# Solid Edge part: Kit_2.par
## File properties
Sűrűség: 0,000 kg/m^3
Pontosság: 0,990
Author: bmolnar
Last saved by: bmolnar
Revision: 77
Username: bmolnar
Dokumentum tartalom típus: 0
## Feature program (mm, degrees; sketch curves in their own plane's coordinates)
base feature "unnamed BaseFeature 1"
thread "unnamed Thread 1"
thread "unnamed Thread 2"
thread "unnamed Thread 3"
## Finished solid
Body 1: solid body, 331 faces, 789 edges, 478 vertices, 4 internal voids.
  Faces by surface: plane 145, cylinder 82, swept 53, cone 28, torus 22, spline 1
  Edges by curve: line 445, circle 187, spline 118, ellipse 28, curve on surface 10, intersection 1
Bounding box of the edges (mm; curved faces can reach further): 65.500 x 65.500 x 14.500, from (-32.75, -32.75, 80.5) to (32.75, 32.75, 95).
Cylindrical faces by radius (mm): R0.2 x40, R0.201 x2, R0.2012 x2, R1.75 x1, R2.5402 x12, R2.6 x4, R3.3235 x2, R3.75 x4, R3.85 x4, R4.283 x1, R5 x2, R5.25 x2, R6 x2, R8.27 x1, R8.85 x1, R9 x1, R15.5811 x1
Conical faces (half-angle, radius in mm at the cone's reference point): 0.5 deg R6.5 x2, 0.5 deg R8 x4, 14 deg R8.135 x1, 14 deg R8.4811 x1, 15 deg R5.067 x4, 15 deg R5.933 x4, 17 deg R8.135 x1, 23 deg R8.829 x1, 42.5 deg R8.1233 x1, 45 deg R3.6735 x4, 45 deg R6.05 x2, 45 deg R9 x1, 84 deg R8.4608 x1, 87 deg R8.1765 x1
Toroidal faces (ring radius, tube radius in mm): R2.9402 r0.4 x12, R3.55 r0.2 x8, R8.8057 r0.2025 x1, R9.2522 r0.2925 x1
Planar faces by outward normal: +x 12, +y 14, +z 24, -x 14, -y 14, -z 1, oblique 66
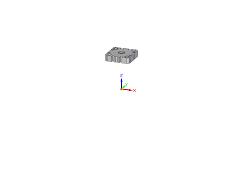
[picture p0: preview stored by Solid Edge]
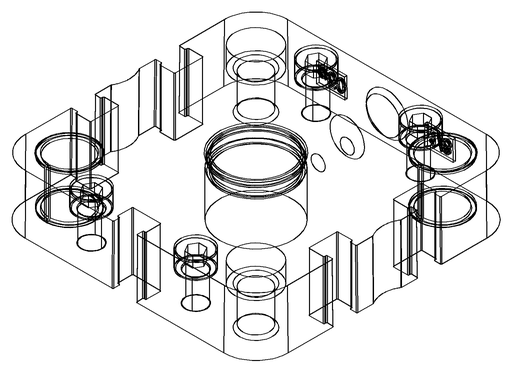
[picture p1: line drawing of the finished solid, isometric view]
